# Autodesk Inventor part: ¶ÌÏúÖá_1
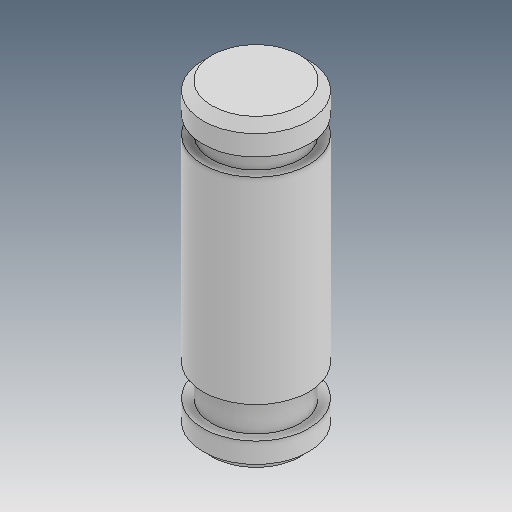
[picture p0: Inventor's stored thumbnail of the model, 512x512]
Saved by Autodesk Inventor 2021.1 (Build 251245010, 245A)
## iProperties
Created: 2019-04
Part Number: ¶ÌÏúÖá_1
Material: Ogólny
Document SubType Name: Modeling
Designer: user
Density: 1 g/cm^3
Appearance: Domyślna
Author: user
Revision Number: ÈÎºÎ
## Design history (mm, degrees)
feature "ÊäÈë1"
node "Bryła1"
